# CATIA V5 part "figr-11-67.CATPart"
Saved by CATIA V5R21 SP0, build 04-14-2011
Part number: Part2
Bounding box of the stored display mesh (mm): x -69 to 69, y -70.588 to 84.546, z -60.219 to 83.037
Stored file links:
  D:\CATIA V5R21 E-RESOURCES\CATIA-V5R21\catia-v5r21-prt\c11-catia-v5r21-prt\c11-catia-v5r21-figr-11-63.CATPart
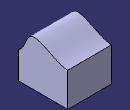
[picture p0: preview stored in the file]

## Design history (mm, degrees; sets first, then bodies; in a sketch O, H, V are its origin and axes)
Set1
  Extrude1: Element1 Sketch2, Lim1 134, Lim2 101, Direction yz-plane
Body1 (main body)
  Sketch1 on yz-plane, origin (0, 0, 0), H (0, 1, 0), V (0, 0, 1)
    line L1 (-70.5879, 56.2311) -> (84.546, 56.2311)
    line L2 (84.546, 56.2311) -> (84.546, -60.2191)
    line L3 (84.546, -60.2191) -> (-70.5879, -60.2191)
    line L4 (-70.5879, -60.2191) -> (-70.5879, 56.2311)
    horizontal: L1 H, L3 H
    vertical: L2 V, L4 V
  Pad1: profile Sketch1, direction (1, 0, 0), length 69, mirrored extent
  SewSurface1: SewingRemoveFace face of Pad1, SplitPlane Extrude1
  Sketch2 on yz-plane, origin (0, 0, 0), H (0, 1, 0), V (0, 0, 1)
    spline S1 through (-101.2957, 16.3509) (-51.8443, 49.0526) (-38.418, 74.5863) (34.1283, 62.9515) (100.0993, 49.0526)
